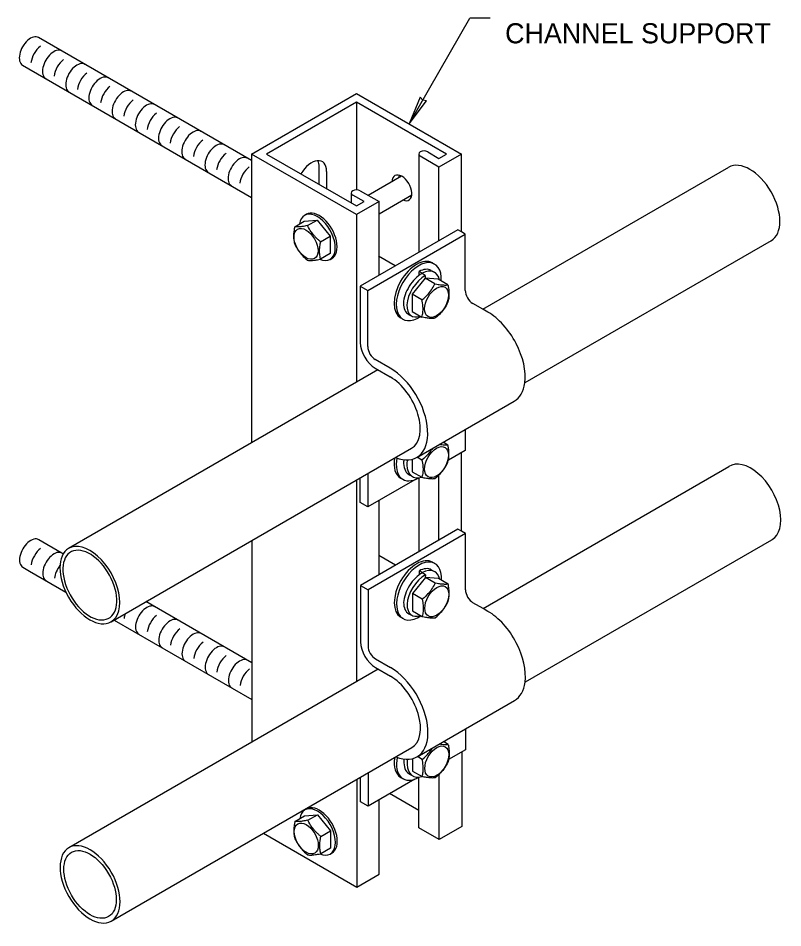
# Model space of a CAD drawing. Extents: x 99862 to 103151, y 100000 to 102076.
# Drawn here: x 100823 to 101432, y 100733 to 101457 of the extents above; entities that cross this region are included whole.
import ezdxf

# ---------------------------------------------------------------- set-up
doc = ezdxf.new("R2010")
doc.units = 0
for name, color, linetype in [('Level 1', 7, 'Continuous'), ('Level 15', 7, 'Continuous'), ('Level 2', 7, 'Continuous'), ('Level 20', 7, 'Continuous'), ('Level 4', 7, 'Continuous'), ('Level 5', 7, 'Continuous'), ('Level 6', 7, 'Continuous'), ('Level 8', 7, 'Continuous'), ('Level 9', 7, 'Continuous')]:
    doc.layers.add(name, color=color, linetype=linetype)

msp = doc.modelspace()

# ---------------------------------------------------------------- linework, layer by layer
at = {"layer": 'Level 1'}
for p, q in [((101009.22, 101348.41), (101092.74, 101396.63)), ((101092.74, 101396.63), (101176.27, 101348.41)), ((101092.74, 101389.74), (101021.15, 101348.41)), ((101092.74, 101389.74), (101092.74, 101319.85)), ((101164.34, 101348.41), (101092.74, 101389.74)), ((101092.74, 101300.18), (101009.22, 101348.41)), ((101009.22, 101348.41), (101009.22, 101118.7)), ((101021.15, 101348.41), (101092.74, 101307.07)), ((101142.21, 101348.41), (101142.21, 101270.18)), ((101158.37, 101338.07), (101143.43, 101346.7)), ((101149.4, 101350.14), (101158.37, 101344.96)), ((101176.27, 101348.41), (101158.37, 101338.07)), ((101158.37, 101344.96), (101164.34, 101348.41)), ((101176.27, 101286.4), (101176.27, 101348.41)), ((101062.91, 101324.29), (101062.91, 101338.07)), ((101068.88, 101334.63), (101068.88, 101320.85)), ((101158.37, 101279.51), (101158.37, 101338.07)), ((101095.7, 101319.14), (101110.64, 101310.52)), ((101088.51, 101317.4), (101088.51, 101309.51)), ((101098.71, 101310.52), (101089.74, 101315.7)), ((101110.64, 101310.52), (101092.74, 101300.18)), ((101092.74, 101307.07), (101098.71, 101310.52)), ((101110.64, 101251.95), (101110.64, 101310.52)), ((101092.74, 101300.18), (101092.74, 101166.92)), ((101176.27, 101048.29), (101176.27, 101110.73)), ((101092.74, 101088.98), (101092.74, 100928.59)), ((101142.21, 101090.72), (101142.21, 101031.85)), ((101158.37, 101041.18), (101158.37, 101093.08)), ((101110.64, 101013.62), (101110.64, 101072.84)), ((101009.41, 101040.86), (101009.41, 100880.47)), ((101176.46, 100872.5), (101176.46, 100813.14)), ((101158.56, 100802.81), (101158.56, 100854.86)), ((101092.93, 100850.76), (101092.93, 100764.92)), ((101142.4, 100812.14), (101142.4, 100852.57)), ((101110.83, 100775.25), (101110.83, 100834.61)), ((101142.4, 100825.92), (101119.09, 100839.38)), ((101158.56, 100802.81), (101142.4, 100812.14)), ((101176.46, 100813.14), (101158.56, 100802.81)), ((101018.6, 100807.84), (101092.93, 100764.92)), ((101092.93, 100764.92), (101110.83, 100775.25))]:
    msp.add_line(p, q, dxfattribs=at)
for centre, major_axis, start_param, end_param in [((101146.39, 101348.41), (-4.19, 0), 5.497787, 7.068583), ((101146.44, 101348.43), (-4.19, 0), 3.926991, 5.497787), ((101056.94, 101327.74), (8.44, 14.61), 5.497787, 7.853982), ((101050.98, 101331.18), (-8.44, -14.61), 2.356194, 2.780226), ((101128.87, 101321.49), (5.59, -9.69), 5.605091, 10.177712), ((101134.15, 101324.54), (-5.59, 9.69), 0.490883, 0.752934), ((101092.69, 101317.4), (-4.19, 0), 5.497787, 7.068583), ((101092.74, 101317.43), (-4.19, 0), 3.926991, 5.497787), ((101134.15, 101324.54), (-5.59, 9.69), 2.463499, 2.65071)]:
    msp.add_ellipse(centre, major_axis=major_axis, ratio=0.57735, start_param=start_param, end_param=end_param, dxfattribs=at)
at = {"layer": 'Level 15'}
for p in [(101134.51, 101372.52), (101199.01, 101456.52)]:
    msp.add_line(p, (101183.01, 101456.52), dxfattribs=at)
msp.add_lwpolyline([(101134.51, 101372.52), (101148.51, 101390.8), (101145.39, 101391.37), (101143.34, 101393.78)], close=True, dxfattribs=at)
at = {"layer": 'Level 2'}
for p, q in [((101173.29, 101288.12), (101095.73, 101243.34)), ((101101.69, 101239.9), (101179.25, 101284.68)), ((101176.27, 101286.4), (101173.29, 101288.12)), ((101179.25, 101284.68), (101176.27, 101286.4)), ((101176.27, 101286.4), (101176.27, 101286.4)), ((101179.25, 101239.9), (101179.25, 101284.68)), ((101095.73, 101243.34), (101101.69, 101239.9)), ((101095.73, 101243.34), (101095.73, 101198.56)), ((101101.69, 101195.12), (101101.69, 101239.9)), ((101193.3, 101224.9), (101185.22, 101229.56)), ((101197.15, 101222.68), (101193.3, 101224.9)), ((101119.59, 101177.9), (101107.66, 101184.78)), ((101107.66, 101177.9), (101119.59, 101171.01)), ((101179.25, 101129.18), (101218.24, 101151.69)), ((101140.68, 101106.91), (101179.25, 101129.18)), ((101179.25, 101129.18), (101179.25, 101112.45)), ((101179.25, 101112.45), (101165.85, 101104.71)), ((101101.69, 101094.14), (101101.69, 101067.67)), ((101095.73, 101071.11), (101095.73, 101090.7)), ((101139.01, 101089.22), (101101.69, 101067.67)), ((101101.69, 101067.67), (101095.73, 101071.11)), ((101173.48, 101049.9), (101095.92, 101005.12)), ((101176.26, 101048.29), (101173.48, 101049.9)), ((101179.45, 101046.46), (101101.88, 101001.68)), ((101179.45, 101046.46), (101176.26, 101048.29)), ((101179.45, 101001.68), (101179.45, 101046.46)), ((101095.92, 101005.12), (101101.88, 101001.68)), ((101095.92, 101005.12), (101095.92, 100960.34)), ((101101.88, 101001.68), (101101.88, 100956.9)), ((101193.49, 100986.68), (101185.41, 100991.34)), ((101193.49, 100986.68), (101193.49, 100986.68)), ((101197.34, 100984.45), (101193.49, 100986.68)), ((101107.85, 100946.56), (101119.78, 100939.67)), ((101107.85, 100939.67), (101119.78, 100932.78)), ((101179.45, 100890.96), (101218.44, 100913.47)), ((101140.88, 100868.69), (101179.45, 100890.96)), ((101179.45, 100890.96), (101179.45, 100874.23)), ((101179.45, 100874.23), (101166.05, 100866.49)), ((101101.88, 100855.92), (101101.88, 100829.45)), ((101095.92, 100832.89), (101095.92, 100852.48)), ((101139.21, 100850.99), (101101.88, 100829.45)), ((101101.88, 100829.45), (101095.92, 100832.89))]:
    msp.add_line(p, q, dxfattribs=at)
for centre, major_axis, start_param, end_param in [((101185.22, 101236.45), (-4.22, 7.31), 0.785398, 2.356194), ((101197.15, 101188.23), (21.09, -36.54), 0.640306, 2.356194), ((101107.66, 101191.67), (-8.44, 14.61), 0.785398, 2.356194), ((101107.66, 101191.67), (-4.22, 7.31), 0.785398, 2.356194), ((101119.59, 101143.45), (21.09, -36.54), 5.639684, 8.63938), ((101119.59, 101143.45), (16.88, -29.23), 0, 2.356194), ((101197.15, 101188.23), (21.09, -36.54), 6.283185, 6.923491), ((101185.41, 100998.23), (-4.22, 7.31), 0.785398, 2.356194), ((101197.34, 100950.01), (21.09, -36.54), 0.640817, 2.356194), ((101107.85, 100953.45), (-8.44, 14.61), 0.785398, 2.356194), ((101107.85, 100953.45), (-4.22, 7.31), 0.785398, 2.356194), ((101119.78, 100905.23), (21.09, -36.54), 5.639684, 8.63938), ((101119.78, 100905.23), (16.88, -29.23), 6.283185, 8.63938), ((101197.34, 100950.01), (21.09, -36.54), 0, 0.640817)]:
    msp.add_ellipse(centre, major_axis=major_axis, ratio=0.57735, start_param=start_param, end_param=end_param, dxfattribs=at)
at = {"layer": 'Level 4'}
for p, q in [((101128.62, 101330.77), (101102.09, 101315.45)), ((101110.64, 101300.91), (101136.74, 101315.97)), ((101043.48, 101290.52), (101051.15, 101294.95)), ((101051.15, 101294.95), (101061.48, 101295.87)), ((101053.81, 101291.45), (101061.48, 101295.87)), ((101061.48, 101295.87), (101071.82, 101283.02)), ((101064.14, 101278.59), (101071.82, 101283.02)), ((101071.82, 101283.02), (101071.82, 101269.24)), ((101071.82, 101269.24), (101064.14, 101264.81)), ((101123.55, 101259.41), (101110.32, 101267.05)), ((101147.46, 101249.64), (101137.13, 101236.79)), ((101155.13, 101245.21), (101147.46, 101249.64)), ((101157.8, 101248.72), (101147.46, 101249.64)), ((101165.47, 101244.29), (101157.8, 101248.72)), ((101144.8, 101232.36), (101137.13, 101236.79)), ((101137.13, 101236.79), (101137.13, 101223.01)), ((101137.13, 101223.01), (101144.8, 101218.58)), ((101165.47, 101116.84), (101161.67, 101119.03)), ((101137.13, 101105.46), (101137.13, 101095.56)), ((101144.8, 101104.91), (101141, 101107.1)), ((101137.13, 101095.56), (101144.8, 101091.13)), ((101123.75, 101021.19), (101110.51, 101028.83)), ((101147.65, 101011.42), (101137.32, 100998.56)), ((101155.33, 101006.99), (101147.65, 101011.42)), ((101157.99, 101010.5), (101147.65, 101011.42)), ((101165.66, 101006.07), (101157.99, 101010.5)), ((101144.99, 100994.14), (101137.32, 100998.56)), ((101137.32, 100998.56), (101137.32, 100984.79)), ((101137.32, 100984.79), (101144.99, 100980.36)), ((101165.66, 100878.62), (101161.86, 100880.81)), ((101144.99, 100866.69), (101141.2, 100868.88)), ((101137.32, 100867.24), (101137.32, 100857.34)), ((101137.32, 100857.34), (101144.99, 100852.91)), ((101043.67, 100817.3), (101051.34, 100821.73)), ((101051.34, 100821.73), (101061.67, 100822.65)), ((101054, 100818.22), (101061.67, 100822.65)), ((101061.67, 100822.65), (101072.01, 100809.8)), ((101064.34, 100805.37), (101072.01, 100809.8)), ((101072.01, 100809.8), (101072.01, 100796.02)), ((101072.01, 100796.02), (101064.34, 100791.59))]:
    msp.add_line(p, q, dxfattribs=at)
for centre, major_axis in [((101052.53, 101276.93), (6.75, -11.69)), ((101156.41, 101230.7), (6.75, 11.69)), ((101156.41, 101103.25), (6.75, 11.69)), ((101156.6, 100992.47), (6.75, 11.69)), ((101156.6, 100865.02), (6.75, 11.69)), ((101052.72, 100803.71), (6.75, -11.69))]:
    msp.add_ellipse(centre, major_axis=major_axis, ratio=0.57735, dxfattribs=at)
for points in [[(101043.48, 101290.52), (101043.22, 101289.25), (101043, 101287.97), (101042.7, 101285.5), (101042.62, 101284.3), (101042.62, 101281.97), (101042.7, 101280.84), (101043, 101278.72), (101043.22, 101277.71), (101043.48, 101276.74)], [(101053.81, 101291.45), (101052.7, 101291.22), (101051.63, 101291.02), (101049.61, 101290.69), (101048.66, 101290.57), (101046.03, 101290.33), (101044.65, 101290.37), (101043.48, 101290.52)], [(101064.14, 101278.59), (101063.04, 101279.49), (101061.97, 101280.43), (101059.95, 101282.4), (101058.99, 101283.44), (101056.36, 101286.71), (101054.98, 101289.04), (101053.81, 101291.45)], [(101043.48, 101276.74), (101044.06, 101275.54), (101044.7, 101274.36), (101046.12, 101272.04), (101046.92, 101270.9), (101049.55, 101267.63), (101051.6, 101265.69), (101053.81, 101263.89)], [(101064.14, 101264.81), (101063.89, 101265.78), (101063.67, 101266.78), (101063.37, 101268.91), (101063.29, 101270.04), (101063.29, 101272.36), (101063.37, 101273.57), (101063.67, 101276.04), (101063.88, 101277.31), (101064.14, 101278.59)], [(101053.81, 101263.89), (101054.4, 101263.81), (101055.03, 101263.77), (101056.46, 101263.75), (101057.25, 101263.78), (101059.88, 101264.01), (101061.93, 101264.36), (101064.14, 101264.81)], [(101144.8, 101232.36), (101147.01, 101234.16), (101149.06, 101236.1), (101152.57, 101240.46), (101153.96, 101242.8), (101155.13, 101245.21)], [(101155.13, 101245.21), (101157.35, 101244.76), (101159.39, 101244.41), (101162.9, 101244.1), (101164.3, 101244.14), (101165.47, 101244.29)], [(101165.47, 101244.29), (101165.73, 101243.01), (101165.95, 101241.74), (101166.24, 101239.27), (101166.32, 101238.06), (101166.32, 101235.73), (101166.24, 101234.61), (101165.94, 101232.48), (101165.73, 101231.48), (101165.47, 101230.51)], [(101144.8, 101218.58), (101145.06, 101219.55), (101145.27, 101220.55), (101145.57, 101222.67), (101145.65, 101223.8), (101145.66, 101226.13), (101145.58, 101227.33), (101145.28, 101229.81), (101145.06, 101231.08), (101144.8, 101232.36)], [(101165.47, 101230.51), (101164.3, 101228.1), (101162.92, 101225.78), (101159.41, 101221.42), (101157.35, 101219.46), (101155.13, 101217.66)], [(101155.13, 101217.66), (101153.96, 101217.5), (101152.58, 101217.47), (101149.08, 101217.78), (101147.02, 101218.13), (101144.8, 101218.58)], [(101165.47, 101116.84), (101164.3, 101116.69), (101162.92, 101116.65), (101160.32, 101116.88), (101159.4, 101117), (101158.42, 101117.16)], [(101165.47, 101103.06), (101165.73, 101104.04), (101165.95, 101105.06), (101166.24, 101107.19), (101166.32, 101108.3), (101166.32, 101110.63), (101166.24, 101111.85), (101165.94, 101114.32), (101165.73, 101115.57), (101165.47, 101116.84)], [(101153.12, 101114.09), (101152.43, 101112.98), (101151.67, 101111.9), (101149.08, 101108.67), (101147.02, 101106.71), (101144.8, 101104.91)], [(101144.8, 101104.91), (101145.06, 101103.64), (101145.27, 101102.39), (101145.57, 101099.92), (101145.65, 101098.69), (101145.66, 101096.37), (101145.58, 101095.25), (101145.28, 101093.13), (101145.06, 101092.1), (101144.8, 101091.13)], [(101155.13, 101090.21), (101157.35, 101092.01), (101159.39, 101093.95), (101162.9, 101098.31), (101164.3, 101100.65), (101165.47, 101103.06)], [(101144.8, 101091.13), (101147.01, 101090.68), (101149.06, 101090.33), (101152.57, 101090.02), (101153.96, 101090.05), (101155.13, 101090.21)], [(101155.33, 101006.99), (101154.16, 101004.58), (101152.76, 101002.24), (101149.25, 100997.88), (101147.21, 100995.94), (101144.99, 100994.14)], [(101165.66, 101006.07), (101164.49, 101005.92), (101163.1, 101005.88), (101159.59, 101006.19), (101157.54, 101006.54), (101155.33, 101006.99)], [(101165.66, 100992.29), (101165.92, 100993.26), (101166.13, 100994.26), (101166.43, 100996.38), (101166.51, 100997.51), (101166.52, 100999.84), (101166.44, 101001.05), (101166.14, 101003.52), (101165.92, 101004.79), (101165.66, 101006.07)], [(101144.99, 100994.14), (101145.25, 100992.86), (101145.47, 100991.58), (101145.77, 100989.11), (101145.85, 100987.91), (101145.85, 100985.58), (101145.76, 100984.45), (101145.47, 100982.33), (101145.25, 100981.32), (101144.99, 100980.36)], [(101155.33, 100979.43), (101157.54, 100981.24), (101159.6, 100983.19), (101163.11, 100987.56), (101164.49, 100989.88), (101165.66, 100992.29)], [(101144.99, 100980.36), (101147.21, 100979.9), (101149.27, 100979.56), (101152.77, 100979.24), (101154.16, 100979.28), (101155.33, 100979.43)], [(101158.62, 100878.93), (101159.59, 100878.78), (101160.51, 100878.66), (101163.11, 100878.43), (101164.49, 100878.47), (101165.66, 100878.62)], [(101165.66, 100878.62), (101165.92, 100877.35), (101166.13, 100876.1), (101166.43, 100873.63), (101166.51, 100872.41), (101166.52, 100870.08), (101166.44, 100868.97), (101166.14, 100866.84), (101165.92, 100865.81), (101165.66, 100864.84)], [(101144.99, 100866.69), (101147.21, 100868.49), (101149.27, 100870.45), (101151.87, 100873.68), (101152.62, 100874.76), (101153.31, 100875.87)], [(101144.99, 100852.91), (101145.25, 100853.88), (101145.47, 100854.9), (101145.77, 100857.03), (101145.85, 100858.14), (101145.85, 100860.47), (101145.76, 100861.7), (101145.47, 100864.17), (101145.25, 100865.42), (101144.99, 100866.69)], [(101165.66, 100864.84), (101164.49, 100862.43), (101163.1, 100860.09), (101159.59, 100855.73), (101157.54, 100853.79), (101155.33, 100851.98)], [(101155.33, 100851.98), (101154.16, 100851.83), (101152.76, 100851.79), (101149.25, 100852.11), (101147.21, 100852.45), (101144.99, 100852.91)], [(101054, 100818.22), (101052.89, 100818), (101051.83, 100817.8), (101049.8, 100817.47), (101048.85, 100817.35), (101046.22, 100817.11), (101044.84, 100817.15), (101043.67, 100817.3)], [(101064.34, 100805.37), (101063.23, 100806.27), (101062.16, 100807.21), (101060.14, 100809.18), (101059.18, 100810.22), (101056.55, 100813.49), (101055.17, 100815.82), (101054, 100818.22)], [(101043.67, 100817.3), (101043.41, 100816.02), (101043.19, 100814.75), (101042.89, 100812.28), (101042.81, 100811.07), (101042.81, 100808.75), (101042.9, 100807.62), (101043.19, 100805.49), (101043.41, 100804.49), (101043.67, 100803.52)], [(101064.34, 100791.59), (101064.08, 100792.56), (101063.86, 100793.56), (101063.56, 100795.68), (101063.48, 100796.81), (101063.48, 100799.14), (101063.56, 100800.35), (101063.86, 100802.82), (101064.07, 100804.09), (101064.34, 100805.37)], [(101043.67, 100803.52), (101044.25, 100802.32), (101044.89, 100801.13), (101046.32, 100798.82), (101047.11, 100797.68), (101049.74, 100794.41), (101051.79, 100792.47), (101054, 100790.67)], [(101054, 100790.67), (101054.59, 100790.59), (101055.22, 100790.54), (101056.65, 100790.52), (101057.44, 100790.56), (101060.07, 100790.79), (101062.12, 100791.14), (101064.34, 100791.59)]]:
    msp.add_open_spline(points, degree=3, dxfattribs=at)
at = {"layer": 'Level 5'}
for p, q in [((101052.79, 101300.46), (101051.36, 101299.63)), ((101052.79, 101300.46), (101051.36, 101299.63)), ((101071.61, 101264.56), (101073.04, 101265.39)), ((101071.61, 101264.56), (101073.04, 101265.39)), ((101153.13, 101261.82), (101154.92, 101260.79)), ((101129.6, 101216.94), (101127.82, 101217.98)), ((101129.6, 101089.49), (101127.82, 101090.53)), ((101153.32, 101023.6), (101155.11, 101022.57)), ((101129.8, 100978.72), (101128.01, 100979.76)), ((101128.01, 100852.31), (101129.8, 100851.27)), ((101052.98, 100827.24), (101051.55, 100826.41)), ((101071.8, 100791.34), (101073.23, 100792.16))]:
    msp.add_line(p, q, dxfattribs=at)
for centre, major_axis, start_param, end_param in [((101061.48, 101282.1), (10.12, -17.54), 6.283185, 10.060003), ((101062.91, 101282.92), (10.12, -17.54), 6.283185, 9.42479), ((101062.91, 101282.92), (10.12, -17.54), 6.283185, 9.42479), ((101061.48, 101282.1), (10.12, -17.54), 5.62548, 6.283185), ((101140.47, 101239.9), (12.66, 21.92), 0.000006, 3.141593), ((101142.26, 101238.87), (12.66, 21.92), 5.41204, 10.295924), ((101140.47, 101112.45), (12.66, 21.92), 2.157168, 3.141593), ((101142.26, 101111.42), (12.66, 21.92), 2.10764, 3.932392), ((101140.66, 101001.68), (12.66, 21.92), 0.000006, 3.141593), ((101142.45, 101000.64), (12.66, 21.92), 5.41204, 10.295924), ((101140.66, 100874.23), (12.66, 21.92), 2.157168, 3.141593), ((101142.45, 100873.19), (12.66, 21.92), 2.10764, 3.923919), ((101061.67, 100808.87), (10.12, -17.54), 6.283185, 10.060003), ((101063.1, 100809.7), (10.12, -17.54), 6.283185, 9.42479), ((101061.67, 100808.87), (10.12, -17.54), 5.62548, 6.283185)]:
    msp.add_ellipse(centre, major_axis=major_axis, ratio=0.57735, start_param=start_param, end_param=end_param, dxfattribs=at)
at = {"layer": 'Level 6'}
for p, q in [((101142.64, 101251.97), (101142.54, 101254.95)), ((101145.1, 101253.58), (101142.54, 101254.95)), ((101147.39, 101251.77), (101144.85, 101253.41)), ((101145.12, 101253.23), (101145.1, 101253.58)), ((101152.06, 101255.81), (101154.62, 101254.44)), ((101147.39, 101251.77), (101147.27, 101249.4)), ((101134.12, 101220.79), (101136.82, 101219.39)), ((101137.64, 101091.57), (101135.08, 101092.89)), ((101142.83, 101013.75), (101142.73, 101016.73)), ((101145.3, 101015.36), (101142.73, 101016.73)), ((101147.58, 101013.55), (101145.04, 101015.19)), ((101145.31, 101015.01), (101145.3, 101015.36)), ((101152.25, 101017.59), (101154.82, 101016.22)), ((101147.58, 101013.55), (101147.46, 101011.18)), ((101134.31, 100982.57), (101137.02, 100981.17)), ((101137.83, 100853.35), (101135.27, 100854.66))]:
    msp.add_line(p, q, dxfattribs=at)
for centre, major_axis, ratio, start_param, end_param in [((101143.94, 101237.76), (10.61, 16.52), 0.544801, 0.802368, 2.38067), ((101142.8, 101238.49), (9.26, 17.32), 0.597856, 6.283185, 7.031394), ((101145.36, 101237.12), (9.26, 17.32), 0.597856, 5.669032, 7.031394), ((101146.62, 101236.21), (10.61, 16.52), 0.544801, 0.811998, 2.370398), ((101143.14, 101238.24), (-9.02, -17.44), 0.544029, 5.471854, 6.283185), ((101145.85, 101236.84), (-9.02, -17.44), 0.544029, 5.471854, 6.845298), ((101143.26, 101110.6), (-9, -17.45), 0.544801, 5.297068, 5.471187), ((101144.06, 101110.35), (-8.98, -17.47), 0.608892, 5.480166, 6.283185), ((101146.62, 101109.04), (-8.98, -17.47), 0.608892, 5.481165, 6.833013), ((101145.85, 101109.27), (-9, -17.45), 0.544801, 5.227707, 5.471187), ((101144.13, 100999.54), (10.61, 16.52), 0.544801, 0.802368, 2.38067), ((101142.99, 101000.27), (9.26, 17.32), 0.597856, 6.283185, 7.031394), ((101145.56, 100998.9), (9.26, 17.32), 0.597856, 5.669032, 7.031394), ((101146.81, 100997.99), (10.61, 16.52), 0.544801, 0.811998, 2.370398), ((101143.33, 101000.01), (-9.02, -17.44), 0.544029, 5.471854, 6.283185), ((101146.04, 100998.62), (-9.02, -17.44), 0.544029, 5.471854, 6.845298), ((101143.46, 100872.38), (-9, -17.45), 0.544801, 5.297068, 5.471187), ((101144.25, 100872.13), (-8.98, -17.47), 0.608892, 5.480166, 6.283185), ((101146.81, 100870.82), (-8.98, -17.47), 0.608892, 5.481165, 6.833013), ((101146.04, 100871.05), (-9, -17.45), 0.544801, 5.227707, 5.471187)]:
    msp.add_ellipse(centre, major_axis=major_axis, ratio=ratio, start_param=start_param, end_param=end_param, dxfattribs=at)
at = {"layer": 'Level 8'}
for p, q in [((101009.22, 101343.15), (100839.53, 101441.12)), ((100826.87, 101419.2), (101009.22, 101313.92)), ((100857.61, 101031.16), (100839.72, 101041.49)), ((100859.21, 101030.24), (100857.61, 101031.16)), ((100827.06, 101019.57), (100832.29, 101016.55)), ((100832.29, 101016.55), (100861.38, 100999.75)), ((101009.41, 100943.52), (100925.11, 100992.19)), ((100899.79, 100977.58), (101009.41, 100914.29))]:
    msp.add_line(p, q, dxfattribs=at)
for centre, start_param, end_param in [((100833.2, 101430.16), 0, 3.141593), ((100842.44, 101424.82), 0.942075, 2.218001), ((100851.67, 101419.49), 0, 3.141593), ((100860.91, 101414.16), 0.942075, 2.218001), ((100870.15, 101408.83), 0, 3.141593), ((100879.38, 101403.49), 0.942075, 2.218001), ((100888.62, 101398.16), 0, 3.141593), ((100897.86, 101392.83), 0.942075, 2.218001), ((100907.09, 101387.49), 0, 3.141593), ((100916.33, 101382.16), 0.942075, 2.218001), ((100925.57, 101376.83), 0, 3.141593), ((100934.81, 101371.5), 0.942075, 2.218001), ((100944.04, 101366.16), 0, 3.141593), ((100953.28, 101360.83), 0.942075, 2.218001), ((100962.52, 101355.5), 0, 3.141593), ((100971.75, 101350.16), 0.942075, 2.218001), ((100980.99, 101344.83), 0, 3.141593), ((100990.23, 101339.5), 0.942075, 2.218001), ((100999.46, 101334.17), 0, 3.141593), ((101008.7, 101328.83), 0.942075, 2.218001), ((100833.39, 101030.53), 0, 3.141593), ((100842.63, 101025.2), 0.942075, 2.218001), ((100851.87, 101019.86), 0, 3.141593), ((100861.1, 101014.53), 1.311188, 2.218001), ((100851.87, 101019.86), 3.003724, 3.141593), ((100925.76, 100977.2), 0, 3.141593), ((100907.29, 100987.87), 2.971064, 3.141593), ((100916.52, 100982.53), 1.883508, 2.218001), ((100935, 100971.87), 0.942075, 2.218001), ((100944.23, 100966.53), 0, 3.141593), ((100953.47, 100961.2), 0.942075, 2.218001), ((100925.76, 100977.2), 3.003724, 3.141593), ((100962.71, 100955.87), 0, 3.141593), ((100971.95, 100950.54), 0.942075, 2.218001), ((100981.18, 100945.2), 0, 3.141593), ((100990.42, 100939.87), 0.942075, 2.218001), ((100999.66, 100934.54), 0, 3.141593), ((101008.89, 100929.2), 0.942075, 2.218001)]:
    msp.add_ellipse(centre, major_axis=(6.33, 10.96), ratio=0.57735, start_param=start_param, end_param=end_param, dxfattribs=at)
at = {"layer": 'Level 9'}
for p, q in [((101193.3, 101224.9), (101389, 101337.89)), ((101422.75, 101279.43), (101226.67, 101166.22)), ((101109.71, 101176.71), (101009.22, 101118.7)), ((101009.22, 101118.7), (100863.55, 101034.6)), ((101009.4, 101040.86), (101136.47, 101114.22)), ((101193.49, 100986.68), (101389.2, 101099.67)), ((100897.3, 100976.14), (101009.4, 101040.86)), ((101422.95, 101041.21), (101226.86, 100928)), ((101423.51, 101041.56), (101422.95, 101041.21)), ((101109.9, 100938.49), (101009.39, 100880.46)), ((101009.39, 100880.46), (100863.75, 100796.38)), ((101018.6, 100807.84), (101136.66, 100876)), ((100897.5, 100737.92), (101018.6, 100807.84))]:
    msp.add_line(p, q, dxfattribs=at)
for centre, major_axis, start_param, end_param in [((101405.88, 101308.66), (16.87, -29.23), 0.000006, 3.141593), ((101406.63, 101070.79), (16.87, -29.23), 0.000006, 3.175318), ((100880.43, 101005.37), (-16.88, 29.23), 3.137764, 6.286811), ((100880.43, 101005.37), (-16.88, 29.23), 0.003626, 3.137764), ((100880.43, 101005.37), (-15.19, 26.31), 2.905341, 9.186883), ((100880.62, 100767.15), (-16.88, 29.23), 3.141597, 6.283185), ((100880.62, 100767.15), (-16.88, 29.23), 0.000008, 3.132103), ((100880.62, 100767.15), (-16.88, 29.23), 3.132103, 3.141597)]:
    msp.add_ellipse(centre, major_axis=major_axis, ratio=0.57735, start_param=start_param, end_param=end_param, dxfattribs=at)
msp.add_ellipse((100880.62, 100767.15), major_axis=(-14.77, 25.57), ratio=0.57735, dxfattribs=at)

# ---------------------------------------------------------------- texts
at = {"layer": 'Level 20'}
msp.add_text('CHANNEL SUPPORT', height=16, rotation=360, dxfattribs=at).set_placement((101211, 101436.52))

doc.saveas('drawing.dxf')
